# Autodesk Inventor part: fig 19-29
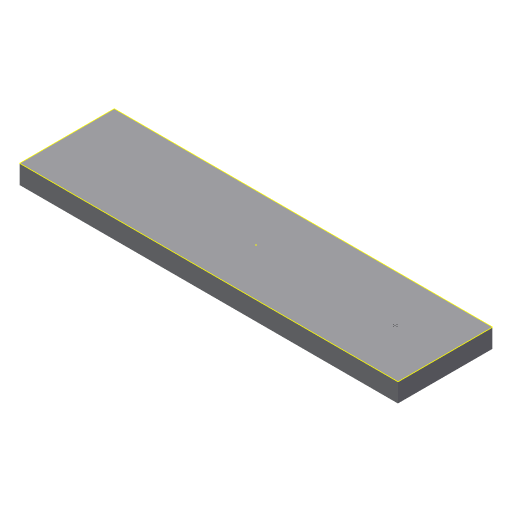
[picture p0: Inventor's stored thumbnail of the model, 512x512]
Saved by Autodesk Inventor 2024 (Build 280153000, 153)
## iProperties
Created: 2013-07
Part Number: fig 19-29
Material: Generic
Document SubType Name: Modeling
Designer: CADCIM
Density: 1 g/cm^3
Appearance: Default
Author: CADCIM
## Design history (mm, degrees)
sketch "Sketch1"
  geometry: L1 (-20, 5)-(20, 5); L2 (20, 5)-(20, -5); L3 (20, -5)-(-20, -5); L4 (-20, -5)-(-20, 5); L5 (-20, 5)-(20, -5); L6 (20, 5)-(-20, -5); 1 further point
  constraints: 12 end point, 2 midpoint, 2 parallel, 1 horizontal, 1 perpendicular
  dimensions: "d0" = 40 distance of L2.end L3.end; "d1" = 10 distance of L1.end L2.end
extrude "Extrusion1" new body sketch "Sketch1" distance "d2" = 2; taper "d3" = 0 deg
sketch "Sketch2"
  geometry: L1 (20, 5)-(-20, 5) reference; L2 (-20, 5)-(-20, -5) reference; L3 (-20, -5)-(20, -5) reference; L4 (20, -5)-(20, 5) reference; 2 further points
body "Solid1"
